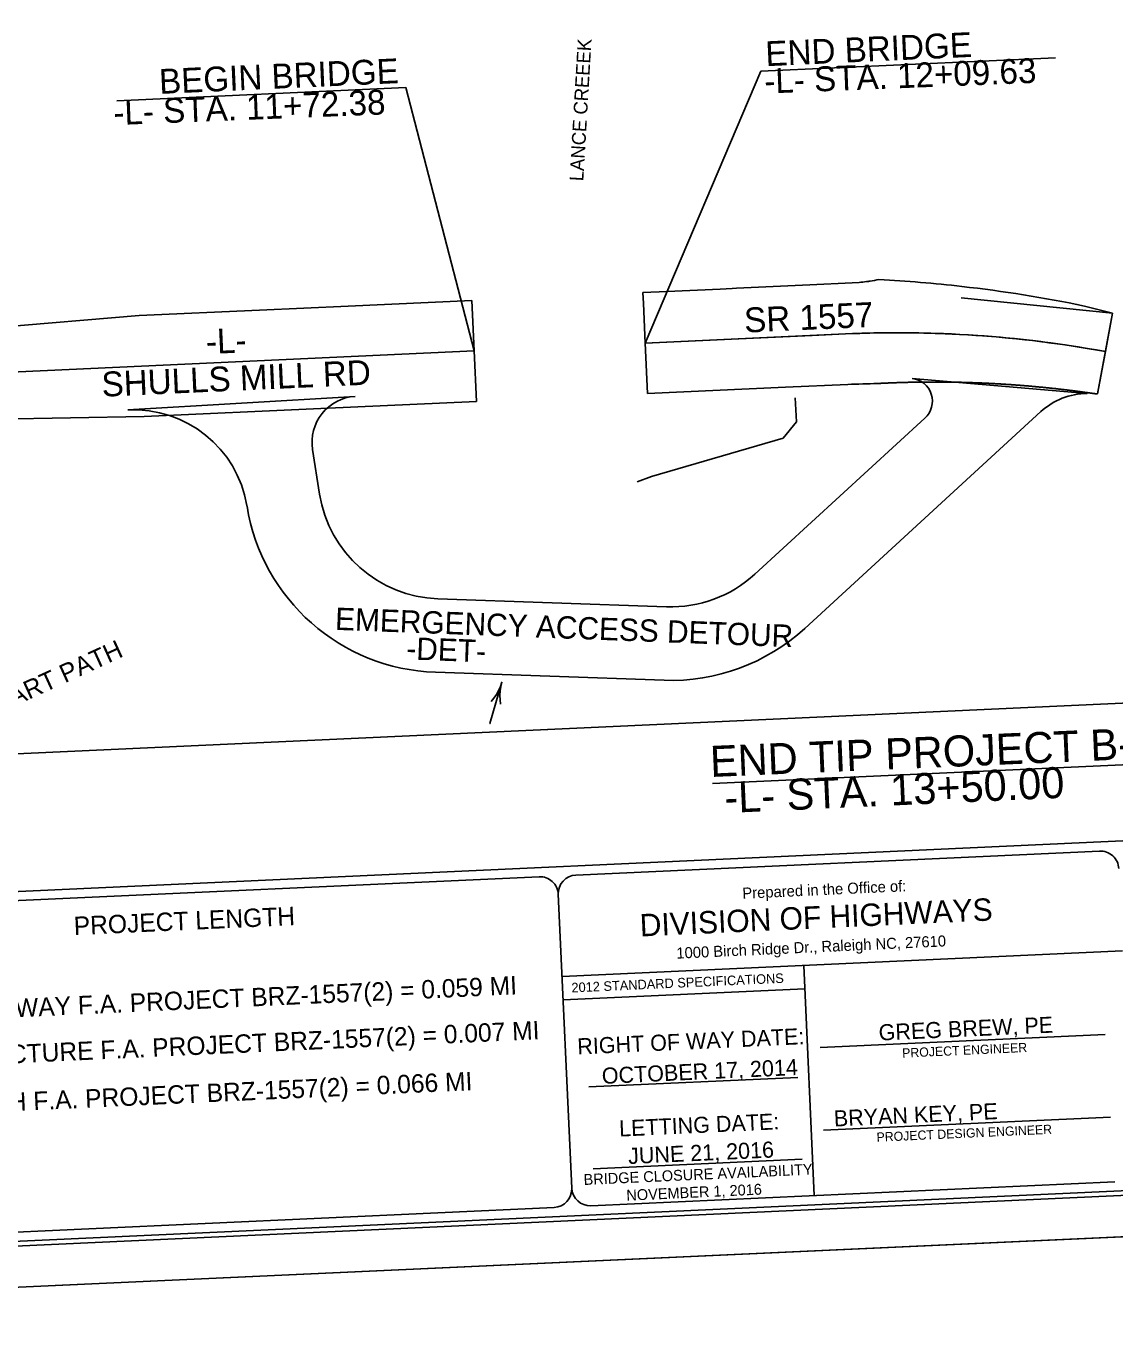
# Model space of a CAD drawing. Extents: x 1190067 to 1192950, y 891516 to 893460.
# Drawn here: x 1192542.6 to 1192779.3, y 892906.1 to 893192.4 of the extents above; entities that cross this region are included whole.
import ezdxf

# ---------------------------------------------------------------- set-up
doc = ezdxf.new("R2010")
doc.units = 0
for name, color, linetype in [('Default', 7, 'Continuous'), ('Prop DSN Text', 7, 'Continuous'), ('Prop Shade Light', 7, 'Continuous'), ('Prop Shade Medium', 7, 'Continuous'), ('Scratch_Level_3', 7, 'Continuous'), ('Sheet Cutting Line CELL', 7, 'Continuous'), ('Sheet Data Field CELL', 7, 'Continuous'), ('Sheet Plot Border Inside CELL', 7, 'Continuous'), ('Sheet Plot Border Outside CELL', 7, 'Continuous'), ('Sheet Title CELL', 7, 'Continuous')]:
    doc.layers.add(name, color=color, linetype=linetype)

msp = doc.modelspace()

# ---------------------------------------------------------------- linework, layer by layer
at = {"layer": 'Default'}
msp.add_line((1192644.71, 893045.27), (1192644.71, 893045.27), dxfattribs=at)
msp.add_lwpolyline([(1192643.68, 893045.56), (1192644.28, 893046.31), (1192644.82, 893047.12), (1192645.29, 893047.97), (1192645.7, 893048.86), (1192645.99, 893049.77), (1192643.43, 893040.77), (1192645.99, 893049.77), (1192645.76, 893048.84), (1192645.64, 893047.87), (1192645.6, 893046.9), (1192645.63, 893045.92), (1192645.74, 893044.97)], dxfattribs=at)
at = {"layer": 'Prop DSN Text'}
for p, q in [((1192702.3, 893182.62), (1192766.39, 893185.55)), ((1192702.3, 893182.62), (1192677.19, 893123.52)), ((1192562.28, 893176.21), (1192625.14, 893179.09)), ((1192625.14, 893179.09), (1192639.97, 893121.82)), ((1192710.06, 893106.39), (1192709.81, 893111.58)), ((1192707.19, 893102.84), (1192710.06, 893106.39)), ((1192678.53, 893094.51), (1192707.19, 893102.84)), ((1192675.42, 893093.32), (1192678.53, 893094.51)), ((1192691.79, 893027.72), (1192809.06, 893033.09))]:
    msp.add_line(p, q, dxfattribs=at)
at = {"layer": 'Prop Shade Light'}
for p, q in [((1192773.28, 893112.55), (1192735.24, 893115.84)), ((1192614.1, 893111.93), (1192564.66, 893109)), ((1192738.02, 893107.19), (1192701.05, 893073.26)), ((1192711.87, 893061.47), (1192763.23, 893108.61)), ((1192606.39, 893090.68), (1192604.86, 893100.39)), ((1192681.85, 893066.17), (1192632.12, 893067.91)), ((1192631.56, 893051.92), (1192681.29, 893050.18))]:
    msp.add_line(p, q, dxfattribs=at)
msp.add_lwpolyline([(1192590.59, 893088.19), (1192590.59, 893088.19)], dxfattribs=at)
for centre, radius, start, end in [((1192734.64, 893110.87), 5, 312.5411, 83.0925), ((1192614.74, 893101.95), 10, 93.6582, 188.9764), ((1192773.37, 893097.56), 15, 90.3526, 132.5411), ((1192565.93, 893084.03), 25, 9.5636, 92.9116), ((1192633.06, 893094.9), 27, 188.9764, 267.9944), ((1192633.06, 893094.9), 43, 188.9764, 189.1922), ((1192565.93, 893084.03), 25, 9.1923, 9.1924), ((1192633.06, 893094.9), 43, 189.1923, 267.9944), ((1192682.79, 893093.16), 27, 267.9944, 312.5411), ((1192682.79, 893093.16), 43, 267.9944, 312.5411)]:
    msp.add_arc(centre, radius, start, end, dxfattribs=at)
at = {"layer": 'Prop Shade Medium'}
for p, q in [((1192713.01, 893136.17), (1192697.03, 893135.44)), ((1192722.2, 893136.59), (1192713.01, 893136.17)), ((1192723.71, 893136.69), (1192722.2, 893136.59)), ((1192681.96, 893134.75), (1192676.68, 893134.51)), ((1192676.68, 893134.51), (1192676.79, 893132.13)), ((1192745.92, 893133.36), (1192778.79, 893130.01)), ((1192639.47, 893132.81), (1192612.58, 893131.57)), ((1192639.97, 893121.82), (1192639.47, 893132.81)), ((1192676.79, 893132.13), (1192677.19, 893123.52)), ((1192778.79, 893130.01), (1192772.72, 893131.58)), ((1192567.12, 893129.5), (1192517.31, 893125.29)), ((1192778.79, 893130.01), (1192775.57, 893112.45)), ((1192777.26, 893121.67), (1192778.79, 893130.01)), ((1192720.75, 893125.51), (1192677.19, 893123.52)), ((1192677.19, 893123.52), (1192697.53, 893124.45)), ((1192697.53, 893124.45), (1192713.52, 893125.18)), ((1192713.52, 893125.18), (1192720.75, 893125.51)), ((1192517.72, 893116.22), (1192639.97, 893121.82)), ((1192639.97, 893121.82), (1192517.72, 893116.22)), ((1192640.48, 893110.83), (1192639.97, 893121.82)), ((1192677.19, 893123.52), (1192677.69, 893112.53)), ((1192775.57, 893112.45), (1192777.26, 893121.67)), ((1192518.16, 893106.67), (1192568.22, 893107.52))]:
    msp.add_line(p, q, dxfattribs=at)
for points in [[(1192697.03, 893135.44), (1192696.11, 893135.4), (1192693.51, 893135.28), (1192681.96, 893134.75)], [(1192612.58, 893131.57), (1192612.58, 893131.57), (1192593.35, 893130.69), (1192567.12, 893129.5)], [(1192677.69, 893112.53), (1192707.7, 893113.9), (1192721.25, 893114.52)], [(1192568.22, 893107.52), (1192593.92, 893108.7), (1192606.65, 893109.28), (1192640.48, 893110.83)]]:
    msp.add_lwpolyline(points, dxfattribs=at)
for centre, radius, start, end in [((1192720.03, 893175.58), 39.06, 275.3979, 277.7646), ((1192720.03, 893175.58), 39.06, 278.914, 281.7955), ((1192712.39, 892839.98), 297.77, 83.5081, 86.9917), ((1192712.39, 892839.98), 297.77, 78.311, 83.5081), ((1192732.17, 892875.77), 250, 79.6108, 92.6195), ((1192732.17, 892875.77), 250, 86.9447, 92.6195), ((1192732.17, 892875.77), 250, 79.6108, 86.9447), ((1192732.17, 892875.77), 239, 91.07, 92.6195)]:
    msp.add_arc(centre, radius, start, end, dxfattribs=at)
for points, degree in [([(1192726.08, 893136.99), (1192725.83, 893136.95), (1192725.57, 893136.91), (1192725.31, 893136.88)], 2), ([(1192727.71, 893114.73), (1192727.93, 893114.74), (1192728.14, 893114.75), (1192728.36, 893114.76), (1192728.57, 893114.78), (1192728.79, 893114.79), (1192729, 893114.8), (1192729.22, 893114.81), (1192729.43, 893114.82), (1192729.65, 893114.82), (1192729.86, 893114.83), (1192730.08, 893114.84), (1192730.29, 893114.85), (1192730.51, 893114.86), (1192730.72, 893114.87), (1192730.94, 893114.88), (1192731.16, 893114.89), (1192731.37, 893114.89), (1192731.59, 893114.9), (1192731.8, 893114.91), (1192732.02, 893114.92), (1192732.23, 893114.92), (1192732.45, 893114.93), (1192732.66, 893114.94), (1192732.88, 893114.94), (1192733.09, 893114.95), (1192733.31, 893114.96), (1192733.53, 893114.96), (1192733.74, 893114.97), (1192733.96, 893114.97), (1192734.17, 893114.98), (1192734.39, 893114.99), (1192734.6, 893114.99), (1192734.82, 893115), (1192735.03, 893115), (1192735.25, 893115), (1192735.47, 893115.01), (1192735.68, 893115.01), (1192735.9, 893115.02), (1192736.11, 893115.02), (1192736.33, 893115.02), (1192736.54, 893115.03), (1192736.76, 893115.03), (1192736.98, 893115.03), (1192737.19, 893115.04), (1192737.41, 893115.04), (1192737.62, 893115.04), (1192737.84, 893115.04), (1192738.05, 893115.05), (1192738.27, 893115.05), (1192738.49, 893115.05), (1192738.7, 893115.05), (1192738.92, 893115.05), (1192739.13, 893115.05), (1192739.35, 893115.05), (1192739.56, 893115.05), (1192739.78, 893115.05), (1192740, 893115.05), (1192740.21, 893115.05), (1192740.43, 893115.05), (1192740.64, 893115.05), (1192740.86, 893115.05), (1192741.07, 893115.05), (1192741.29, 893115.05), (1192741.51, 893115.05), (1192741.72, 893115.05), (1192741.94, 893115.05), (1192742.15, 893115.05), (1192742.37, 893115.04), (1192742.59, 893115.04), (1192742.8, 893115.04), (1192743.02, 893115.04), (1192743.23, 893115.03), (1192743.39, 893115.03), (1192743.55, 893115.03), (1192743.7, 893115.03)], 3), ([(1192743.7, 893115.03), (1192743.76, 893115.03), (1192743.82, 893115.03), (1192743.88, 893115.03), (1192744.1, 893115.02), (1192744.31, 893115.02), (1192744.53, 893115.01), (1192744.74, 893115.01), (1192744.96, 893115.01), (1192745.18, 893115), (1192745.39, 893115), (1192745.61, 893114.99), (1192745.82, 893114.99), (1192746.04, 893114.98), (1192746.26, 893114.98), (1192746.47, 893114.97), (1192746.69, 893114.96), (1192746.9, 893114.96), (1192747.12, 893114.95), (1192747.34, 893114.95), (1192747.55, 893114.94), (1192747.77, 893114.93), (1192747.98, 893114.93), (1192748.2, 893114.92), (1192748.42, 893114.91), (1192748.63, 893114.9), (1192748.85, 893114.9), (1192749.06, 893114.89), (1192749.28, 893114.88), (1192749.5, 893114.87), (1192749.71, 893114.86), (1192749.93, 893114.85), (1192750.14, 893114.85), (1192750.36, 893114.84), (1192750.57, 893114.83), (1192750.79, 893114.82), (1192751.01, 893114.81), (1192751.22, 893114.8), (1192751.44, 893114.79), (1192751.65, 893114.78), (1192751.87, 893114.77), (1192752.09, 893114.76), (1192752.3, 893114.75), (1192752.52, 893114.73), (1192752.73, 893114.72), (1192752.95, 893114.71), (1192753.17, 893114.7), (1192753.38, 893114.69), (1192753.6, 893114.68), (1192753.81, 893114.66), (1192754.03, 893114.65), (1192754.24, 893114.64), (1192754.46, 893114.63), (1192754.68, 893114.61), (1192754.89, 893114.6), (1192755.11, 893114.59), (1192755.32, 893114.57), (1192755.54, 893114.56), (1192755.76, 893114.54), (1192755.97, 893114.53), (1192756.19, 893114.52), (1192756.4, 893114.5), (1192756.62, 893114.49), (1192756.83, 893114.47), (1192757.05, 893114.46), (1192757.27, 893114.44), (1192757.48, 893114.43), (1192757.7, 893114.41), (1192757.91, 893114.39), (1192758.13, 893114.38), (1192758.34, 893114.36), (1192758.56, 893114.34), (1192758.78, 893114.33), (1192758.99, 893114.31), (1192759.21, 893114.29), (1192759.42, 893114.28), (1192759.51, 893114.27), (1192759.59, 893114.26), (1192759.68, 893114.26)], 3), ([(1192759.68, 893114.26), (1192759.81, 893114.25), (1192759.94, 893114.23), (1192760.07, 893114.22), (1192760.29, 893114.21), (1192760.5, 893114.19), (1192760.72, 893114.17), (1192760.93, 893114.15), (1192761.15, 893114.13), (1192761.36, 893114.11), (1192761.58, 893114.09), (1192761.8, 893114.07), (1192762.01, 893114.05), (1192762.23, 893114.03), (1192762.44, 893114.01), (1192762.66, 893113.99), (1192762.87, 893113.97), (1192763.09, 893113.95), (1192763.3, 893113.93), (1192763.52, 893113.91), (1192763.73, 893113.89), (1192763.95, 893113.87), (1192764.17, 893113.85), (1192764.38, 893113.82), (1192764.6, 893113.8), (1192764.81, 893113.78), (1192765.03, 893113.76), (1192765.24, 893113.73), (1192765.46, 893113.71), (1192765.67, 893113.69), (1192765.89, 893113.67), (1192766.1, 893113.64), (1192766.32, 893113.62), (1192766.53, 893113.6), (1192766.75, 893113.57), (1192766.97, 893113.55), (1192767.18, 893113.52), (1192767.4, 893113.5), (1192767.61, 893113.47), (1192767.83, 893113.45), (1192768.04, 893113.42), (1192768.26, 893113.4), (1192768.47, 893113.37), (1192768.69, 893113.35), (1192768.9, 893113.32), (1192769.12, 893113.3), (1192769.33, 893113.27), (1192769.55, 893113.24), (1192769.76, 893113.22), (1192769.98, 893113.19), (1192770.19, 893113.16), (1192770.41, 893113.13), (1192770.62, 893113.11), (1192770.84, 893113.08), (1192771.05, 893113.05), (1192771.27, 893113.02), (1192771.48, 893113), (1192771.7, 893112.97), (1192771.91, 893112.94), (1192772.13, 893112.91), (1192772.34, 893112.88), (1192772.56, 893112.85), (1192772.77, 893112.82), (1192772.99, 893112.79), (1192773.2, 893112.76), (1192773.42, 893112.73), (1192773.63, 893112.7), (1192773.84, 893112.67), (1192774.06, 893112.64), (1192774.27, 893112.61), (1192774.7, 893112.56), (1192775.13, 893112.5), (1192775.57, 893112.45)], 3)]:
    msp.add_open_spline(points, degree=degree, dxfattribs=at)
at = {"layer": 'Scratch_Level_3'}
msp.add_lwpolyline([(1192415.45, 893028.46), (1192896.45, 893050.47), (1192887.89, 893237.54), (1192406.89, 893215.53)], close=True, dxfattribs=at)
at = {"layer": 'Sheet Cutting Line CELL'}
msp.add_line((1192277.54, 892906.14), (1192950.44, 892936.92), dxfattribs=at)
at = {"layer": 'Sheet Plot Border Inside CELL'}
msp.add_lwpolyline([(1192282.33, 892915.34), (1192948.23, 892945.8), (1192928.94, 893367.4), (1192263.04, 893336.94)], close=True, dxfattribs=at)
at = {"layer": 'Sheet Plot Border Outside CELL'}
msp.add_lwpolyline([(1192930.33, 893376.46), (1192257.43, 893345.67), (1192277.54, 892906.14), (1192950.44, 892936.92)], close=True, dxfattribs=at)
at = {"layer": 'Sheet Title CELL'}
for p, q in [((1192366.32, 892996.29), (1192933.72, 893022.25)), ((1192662.1, 893007.82), (1192775.98, 893013.03)), ((1192502.27, 893000.5), (1192654.11, 893007.45)), ((1192658.29, 893003.64), (1192661.21, 892939.71)), ((1192780.98, 892991.33), (1192659.1, 892985.76)), ((1192711.67, 892988.16), (1192713.96, 892938.11)), ((1192711.9, 892983.06), (1192659.34, 892980.66)), ((1192696.76, 892982.37), (1192696.76, 892982.37)), ((1192715.25, 892970.31), (1192777.24, 892973.14)), ((1192710.38, 892963.84), (1192664.93, 892961.76)), ((1192687.64, 892962.79), (1192687.64, 892962.79)), ((1192715.93, 892952.32), (1192778.37, 892955.18)), ((1192711.35, 892946.02), (1192665.9, 892943.94))]:
    msp.add_line(p, q, dxfattribs=at)
for points in [[(1192347.81, 892919.36), (1192939.19, 892946.41)], [(1192665.39, 892935.89), (1192779.27, 892941.1)], [(1192505.56, 892928.57), (1192657.4, 892935.52)]]:
    msp.add_lwpolyline(points, dxfattribs=at)
for centre, start, end in [((1192776.16, 893009.05), 2.6195, 92.6195), ((1192654.29, 893003.47), 2.6195, 92.6195), ((1192662.28, 893003.84), 92.6195, 182.6195), ((1192657.22, 892939.54), 272.6195, 2.6195), ((1192665.21, 892939.91), 182.6195, 272.6195)]:
    msp.add_arc(centre, 4, start, end, dxfattribs=at)

# ---------------------------------------------------------------- texts
at = {"layer": 'Default'}
msp.add_text('LANCE CREEEK', height=3, rotation=86.646, dxfattribs=at).set_placement((1192663.72, 893158.67))
at = {"layer": 'Prop DSN Text'}
for s, height, rotation, p in [('END BRIDGE', 5.4, 2.5982, (1192703.44, 893183.73)), ('BEGIN BRIDGE', 5.4, 2.5982, (1192571.6, 893177.7)), ('-L- STA. 12+09.63', 5.4, 2.2753, (1192703.18, 893177.78)), ('-L- STA. 11+72.38', 5.4, 2.2753, (1192561.64, 893170.92)), ('SR 1557', 5.4, 2.5982, (1192698.82, 893125.79)), ('-L-', 5.4, 2.5982, (1192581.78, 893121.12)), ('SHULLS MILL RD', 5.4, 2.5982, (1192559.1, 893111.85)), ('EMERGENCY ACCESS DETOUR', 4.86, 357.8265, (1192609.68, 893061.16)), ('GOLF CART PATH', 4, 24.5617, (1192521.79, 893036.19)), ('-DET-', 4.86, 357.8265, (1192625.17, 893054.74)), ('END TIP PROJECT B-5118', 6.75, 2.4356, (1192691.43, 893029.15)), ('-L- STA. 13+50.00', 6.75, 2.5888, (1192694.53, 893021.31)), ('LENGTH ROADWAY F.A. PROJECT BRZ-1557(2) = 0.059 MI', 4, 2.6195, (1192501.66, 892975.13)), ('LENGTH STRUCTURE F.A. PROJECT BRZ-1557(2) = 0.007 MI', 4, 2.6195, (1192501.21, 892965.13)), ('TOTAL LENGTH F.A. PROJECT BRZ-1557(2) = 0.066 MI', 4, 2.6195, (1192502.35, 892954.78)), ('BRIDGE CLOSURE AVAILABILITY', 2.362, 2.6195, (1192663.84, 892940.42)), ('NOVEMBER 1, 2016', 2.362, 2.6195, (1192673.14, 892937))]:
    msp.add_text(s, height=height, rotation=rotation, dxfattribs=at).set_placement(p)
at = {"layer": 'Sheet Data Field CELL'}
for s, p in [('GREG BREW, PE               ', (1192728.03, 892971.83)), ('OCTOBER 17, 2014', (1192667.83, 892962.4)), ('       BRYAN KEY, PE        ', (1192709.19, 892952.72)), ('JUNE 21, 2016', (1192673.55, 892944.97))]:
    msp.add_text(s, height=3.5, rotation=2.6195, dxfattribs=at).set_placement(p)
at = {"layer": 'Sheet Title CELL'}
for s, height, p in [('Prepared in the Office of:', 2.3998, (1192698.37, 893002.68)), ('DIVISION OF HIGHWAYS', 4.8749, (1192676.12, 892994.46)), ('PROJECT LENGTH', 3.9998, (1192553.02, 892994.76)), ('1000 Birch Ridge Dr., Raleigh NC, 27610', 2.4, (1192684.02, 892989.64)), ('2012 STANDARD SPECIFICATIONS', 2.08, (1192661.2, 892982.29)), ('RIGHT OF WAY DATE: ', 3.4999, (1192662.5, 892968.81)), ('PROJECT ENGINEER', 1.9998, (1192733.11, 892968.12)), ('LETTING DATE:', 3.4999, (1192671.59, 892950.95)), ('PROJECT DESIGN ENGINEER', 1.9998, (1192727.54, 892949.82))]:
    msp.add_text(s, height=height, rotation=2.6195, dxfattribs=at).set_placement(p)

doc.saveas('drawing.dxf')
